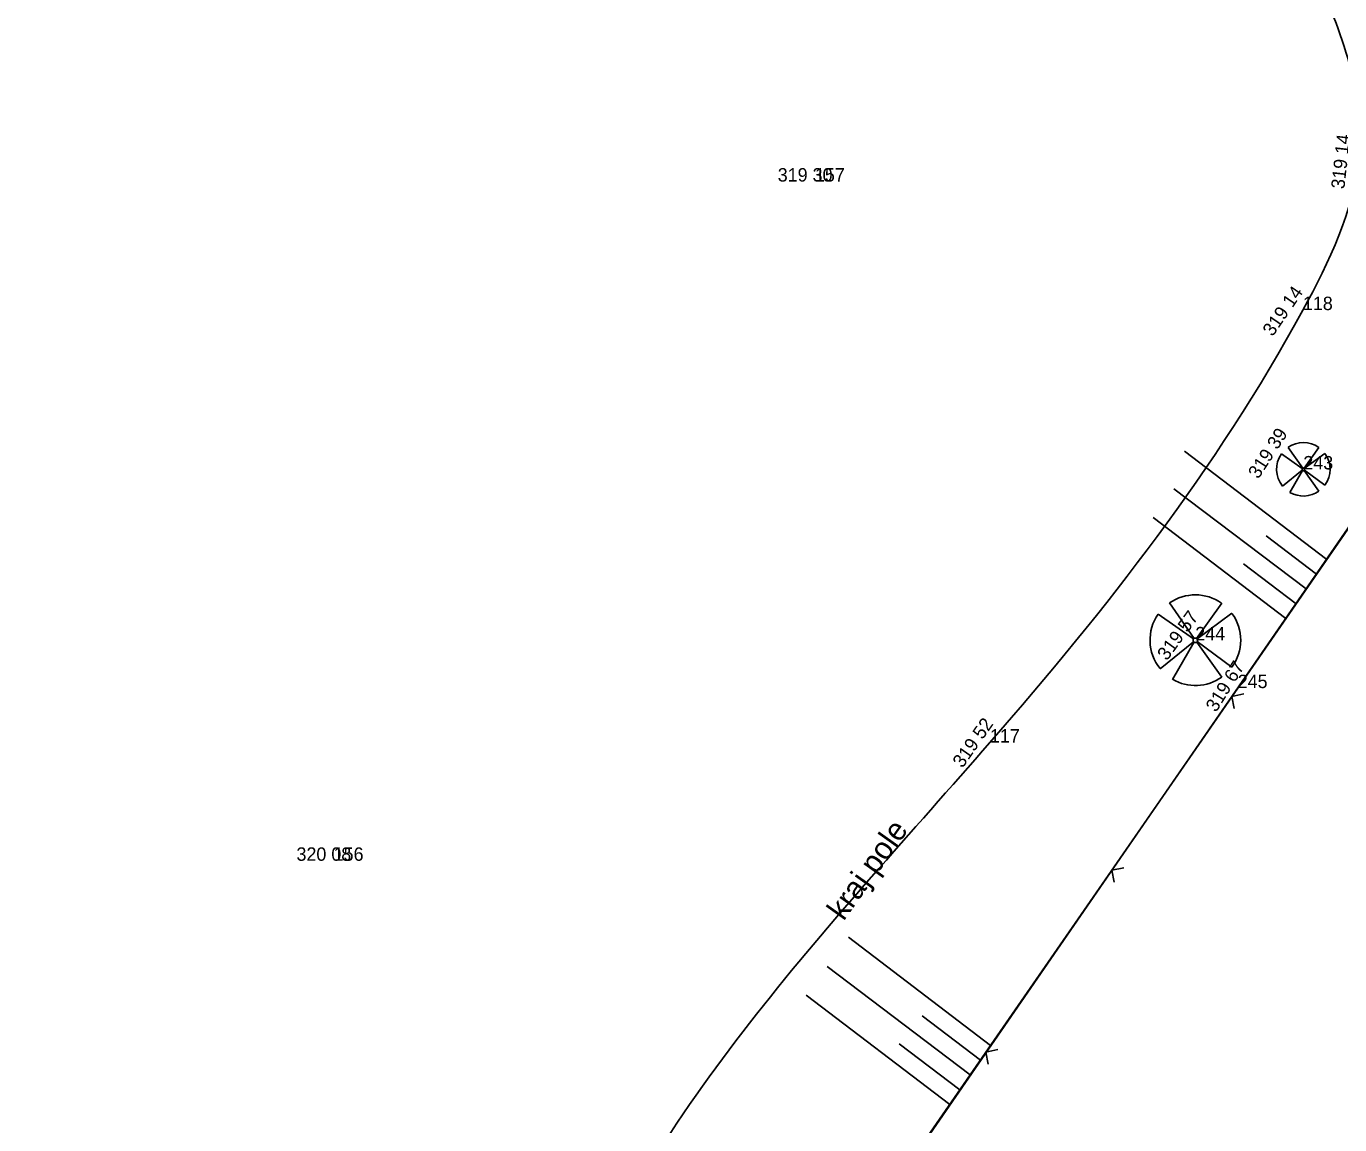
# Model space of a CAD drawing. Extents: x -742884 to -742543, y -1054677 to -1054433.
# Drawn here: x -742706.11 to -742676.68, y -1054548.2 to -1054523.59 of the extents above; entities that cross this region are included whole.
import ezdxf

# ---------------------------------------------------------------- set-up
doc = ezdxf.new("R2010")
doc.units = 0
for name, color, linetype in [('Vrstva 1', 7, 'Continuous'), ('Vrstva 10', 7, 'Continuous'), ('Vrstva 11', 7, 'Continuous'), ('Vrstva 15', 7, 'Continuous'), ('Vrstva 2', 7, 'Continuous'), ('Vrstva 3', 7, 'Continuous'), ('Vrstva 4', 7, 'Continuous'), ('Vrstva 5', 7, 'Continuous'), ('Vrstva 50', 7, 'Continuous')]:
    doc.layers.add(name, color=color, linetype=linetype)

# ---------------------------------------------------------------- blocks, each defined once
blk = doc.blocks.new('Z15')
at = {"layer": 'Vrstva 2'}
for p, q in [((-10, 2), (-8, 6)), ((-10, -2), (-10, 2)), ((-8, 6), (-6, 8)), ((-6, 8), (-2, 10)), ((-2, 10), (2, 10)), ((2, 10), (6, 8)), ((6, 8), (8, 6)), ((8, 6), (10, 2)), ((10, 2), (10, -2)), ((-8, -6), (-10, -2)), ((-6, -8), (-8, -6)), ((-2, -10), (-6, -8)), ((2, -10), (-2, -10)), ((6, -8), (2, -10)), ((8, -6), (6, -8)), ((10, -2), (8, -6))]:
    blk.add_line(p, q, dxfattribs=at)

msp = doc.modelspace()

# ---------------------------------------------------------------- linework, layer by layer
at = {"layer": 'Vrstva 1'}
for p, q in [((-742688.44, -1054527.07), (-742688.44, -1054527.07)), ((-742677.51, -1054529.95), (-742677.51, -1054529.95)), ((-742677.5, -1054533.52), (-742677.5, -1054533.52)), ((-742679.92, -1054537.35), (-742679.92, -1054537.35)), ((-742678.97, -1054538.42), (-742678.97, -1054538.42)), ((-742684.52, -1054539.64), (-742684.52, -1054539.64)), ((-742699.22, -1054542.29), (-742699.22, -1054542.29))]:
    msp.add_line(p, q, dxfattribs=at)
at = {"layer": 'Vrstva 10'}
for p, q in [((-742677.524, -1054533.499), (-742677.99, -1054533.171)), ((-742677.514, -1054533.496), (-742677.841, -1054533.026)), ((-742677.482, -1054533.496), (-742677.151, -1054533.029)), ((-742677.478, -1054533.503), (-742677.018, -1054533.162)), ((-742677.524, -1054533.54), (-742677.967, -1054533.896)), ((-742677.517, -1054533.547), (-742677.802, -1054534.037)), ((-742677.481, -1054533.544), (-742677.151, -1054534.008)), ((-742677.474, -1054533.538), (-742677.018, -1054533.875)), ((-742679.944, -1054537.31), (-742680.498, -1054536.513)), ((-742679.89, -1054537.31), (-742679.329, -1054536.519)), ((-742679.96, -1054537.316), (-742680.748, -1054536.76)), ((-742679.882, -1054537.321), (-742679.102, -1054536.744)), ((-742679.961, -1054537.385), (-742680.71, -1054537.987)), ((-742679.95, -1054537.395), (-742680.431, -1054538.226)), ((-742679.886, -1054537.39), (-742679.328, -1054538.177)), ((-742679.876, -1054537.379), (-742679.102, -1054537.952))]:
    msp.add_line(p, q, dxfattribs=at)
for centre, radius, start, end in [((-742677.5, -1054533.517), 0.6, 144.8767, 218.9336), ((-742677.499, -1054533.518), 0.6, 54.7465, 124.8105), ((-742677.499, -1054533.518), 0.6, 323.4756, 36.2971), ((-742677.499, -1054533.518), 0.6, 239.6151, 305.4552), ((-742679.918, -1054537.347), 1.016, 54.7465, 124.8105), ((-742679.919, -1054537.345), 1.016, 144.8767, 218.9336), ((-742679.918, -1054537.347), 1.016, 323.4756, 36.2971), ((-742679.918, -1054537.347), 1.016, 239.6151, 305.4552)]:
    msp.add_arc(centre, radius, start, end, dxfattribs=at)
at = {"layer": 'Vrstva 11'}
for p, q in [((-742676.975, -1054535.537), (-742680.158, -1054533.113)), ((-742677.433, -1054536.198), (-742680.398, -1054533.954)), ((-742680.863, -1054534.597), (-742677.89, -1054536.86)), ((-742677.205, -1054535.869), (-742678.331, -1054535.012)), ((-742678.843, -1054535.639), (-742677.664, -1054536.532)), ((-742684.505, -1054546.425), (-742687.688, -1054544)), ((-742684.962, -1054547.085), (-742688.167, -1054544.659)), ((-742688.635, -1054545.301), (-742685.42, -1054547.747)), ((-742684.734, -1054546.757), (-742686.041, -1054545.762)), ((-742686.553, -1054546.389), (-742685.193, -1054547.419))]:
    msp.add_line(p, q, dxfattribs=at)
for points in [[(-742776.7, -1054542.68), (-742764.01, -1054527.79), (-742751.11, -1054512.75), (-742737.61, -1054496.47), (-742726.42, -1054483.98), (-742725.9, -1054484.03), (-742714, -1054491.86), (-742704.819, -1054497.481), (-742700.94, -1054500.269), (-742696.44, -1054503.39), (-742688.83, -1054509.5), (-742682.54, -1054514.17), (-742675.15, -1054519.77), (-742673.01, -1054522.11), (-742671.05, -1054524.7)], [(-742641.45, -1054542), (-742646.08, -1054542.32), (-742650.28, -1054545.1), (-742653.63, -1054549.14), (-742658.66, -1054557.13), (-742664.13, -1054565.84), (-742667.81, -1054569.62), (-742669.76, -1054570.07), (-742674.4, -1054567.88), (-742684.66, -1054562.03), (-742693.02, -1054556.88), (-742694.43, -1054554.37), (-742693.99, -1054552.67), (-742684.52, -1054539.64), (-742677.51, -1054529.95), (-742676.26, -1054526.54), (-742677.27, -1054522.39), (-742681.19, -1054517.29), (-742689.28, -1054510.73), (-742697.86, -1054505.14), (-742704.02, -1054502.75), (-742713.11, -1054501.07), (-742723.98, -1054503.51), (-742736.77, -1054510.1), (-742745.39, -1054515.75), (-742752.81, -1054521.82), (-742762.72, -1054531.38), (-742770.54, -1054539.36), (-742775.54, -1054544.64)]]:
    msp.add_spline(points, degree=3, dxfattribs=at)
at = {"layer": 'Vrstva 4'}
msp.add_spline([(-742718.8, -1054478.84), (-742709.4, -1054484.88), (-742695.99, -1054493.43), (-742680.4, -1054503.55), (-742661.01, -1054516), (-742635.78, -1054532.31)], degree=3, dxfattribs=at)
at = {"layer": 'Vrstva 5'}
for p, q in [((-742678.83, -1054538.55), (-742679.099, -1054538.607)), ((-742679.047, -1054538.877), (-742679.099, -1054538.607)), ((-742681.523, -1054542.445), (-742681.792, -1054542.502)), ((-742681.74, -1054542.772), (-742681.792, -1054542.502)), ((-742684.34, -1054546.518), (-742684.609, -1054546.575)), ((-742684.557, -1054546.845), (-742684.609, -1054546.575))]:
    msp.add_line(p, q, dxfattribs=at)
msp.add_lwpolyline([(-742687.06, -1054550.12), (-742678.97, -1054538.42), (-742670.43, -1054526.08)], dxfattribs=at)
at = {"layer": 'Vrstva 50'}
msp.add_lwpolyline([(-742670.45, -1054526.06), (-742684.78, -1054546.85), (-742687.08, -1054550.18), (-742679.03, -1054555.7), (-742669.36, -1054562.14), (-742666.55, -1054557.95), (-742665.76, -1054556.77), (-742666.29, -1054556.4), (-742653.11, -1054537.36), (-742666.64, -1054528.55)], dxfattribs=at)

# ---------------------------------------------------------------- block references
at = {"layer": 'Vrstva 10', "rotation": -30.671756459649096}
for p, xscale, yscale in [((-742677.5, -1054533.52), 0.0029992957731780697, 0.0029992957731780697), ((-742679.92, -1054537.35), 0.005079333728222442, 0.005079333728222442)]:
    msp.add_blockref('Z15', p, dxfattribs=dict(at, xscale=xscale, yscale=yscale))

# ---------------------------------------------------------------- texts
at = {"layer": 'Vrstva 15'}
msp.add_text('kraj pole', height=0.4992, rotation=54.5668, dxfattribs=at).set_placement((-742687.797, -1054543.654))
at = {"layer": 'Vrstva 2'}
for s, p in [('157', (-742688.44, -1054527.07)), ('118', (-742677.51, -1054529.95)), ('243', (-742677.5, -1054533.52)), ('244', (-742679.92, -1054537.35)), ('245', (-742678.97, -1054538.42)), ('117', (-742684.52, -1054539.64)), ('156', (-742699.22, -1054542.29))]:
    msp.add_text(s, height=0.3, dxfattribs=at).set_placement(p)
at = {"layer": 'Vrstva 3'}
for s, rotation, p in [('319 14 ', 83.8082, (-742676.581, -1054527.247)), ('319 14 ', 55.516, (-742678.187, -1054530.557)), ('319 39 ', 57.0223, (-742678.507, -1054533.749)), ('319 57 ', 53.9495, (-742680.554, -1054537.821)), ('319 67 ', 58.0814, (-742679.453, -1054538.976)), ('319 52 ', 54.9885, (-742685.134, -1054540.227))]:
    msp.add_text(s, height=0.3, rotation=rotation, dxfattribs=at).set_placement(p)
for s, p in [('319 30 ', (-742689.273, -1054527.07)), ('320 08 ', (-742700.053, -1054542.29))]:
    msp.add_text(s, height=0.3, dxfattribs=at).set_placement(p)

doc.saveas('drawing.dxf')
